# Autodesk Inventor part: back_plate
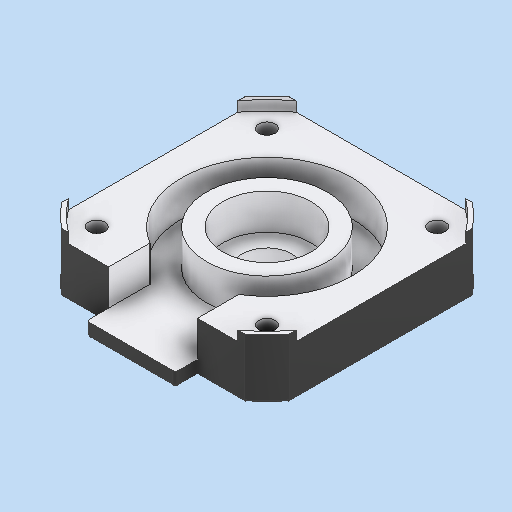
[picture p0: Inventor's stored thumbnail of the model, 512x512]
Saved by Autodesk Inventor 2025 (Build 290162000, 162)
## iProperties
Created: 2025-05
Part Number: back_plate
Material: Generico
Description: back_plate
Document SubType Name: Modeling
Designer: R5800u
Density: 1 g/cm^3
Appearance: Default
Author: R5800u
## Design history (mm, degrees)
feature "Base1"
node "Solido1"
